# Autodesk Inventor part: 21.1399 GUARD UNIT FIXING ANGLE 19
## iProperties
Created: 2007-01
Part Number: 21.1399 GUARD UNIT FIXING ANGLE 19
Material: Steel
Document SubType Name: Modeling
Designer: Andy Moles
Density: 7.85 g/cm^3
Author: Andy Moles
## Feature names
1. Extrusion1
2. Extrusion2
3. Hole1
4. Extrusion3
5. Extrusion4
6. Chamfer1
7. Chamfer2
